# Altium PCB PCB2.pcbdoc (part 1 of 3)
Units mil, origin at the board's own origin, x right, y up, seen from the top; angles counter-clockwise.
Board outline 1771.65 x 2755.61 mil, 4 copper layers (Top Layer, Inner1, Inner2, Bottom Layer), stack 62.447 mil thick; 80 components, 88 nets, 409 pads, 183 vias.
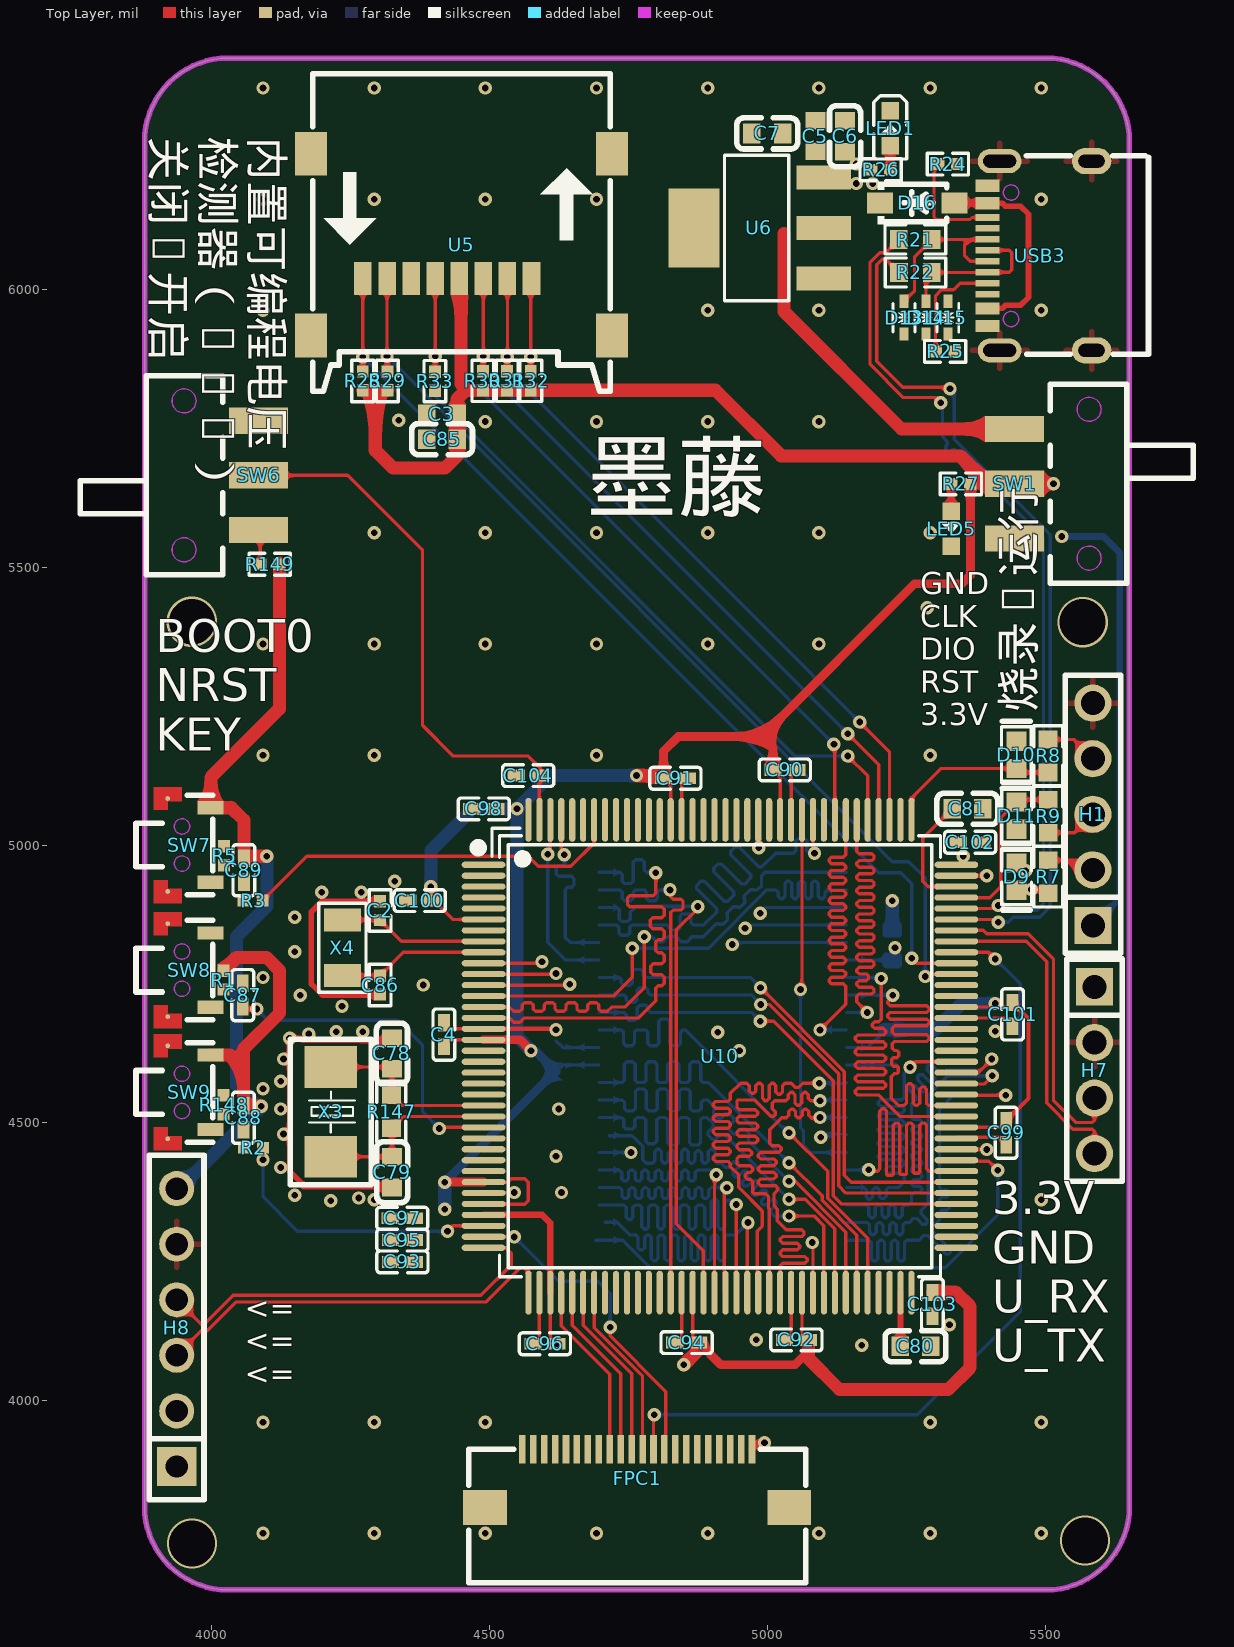
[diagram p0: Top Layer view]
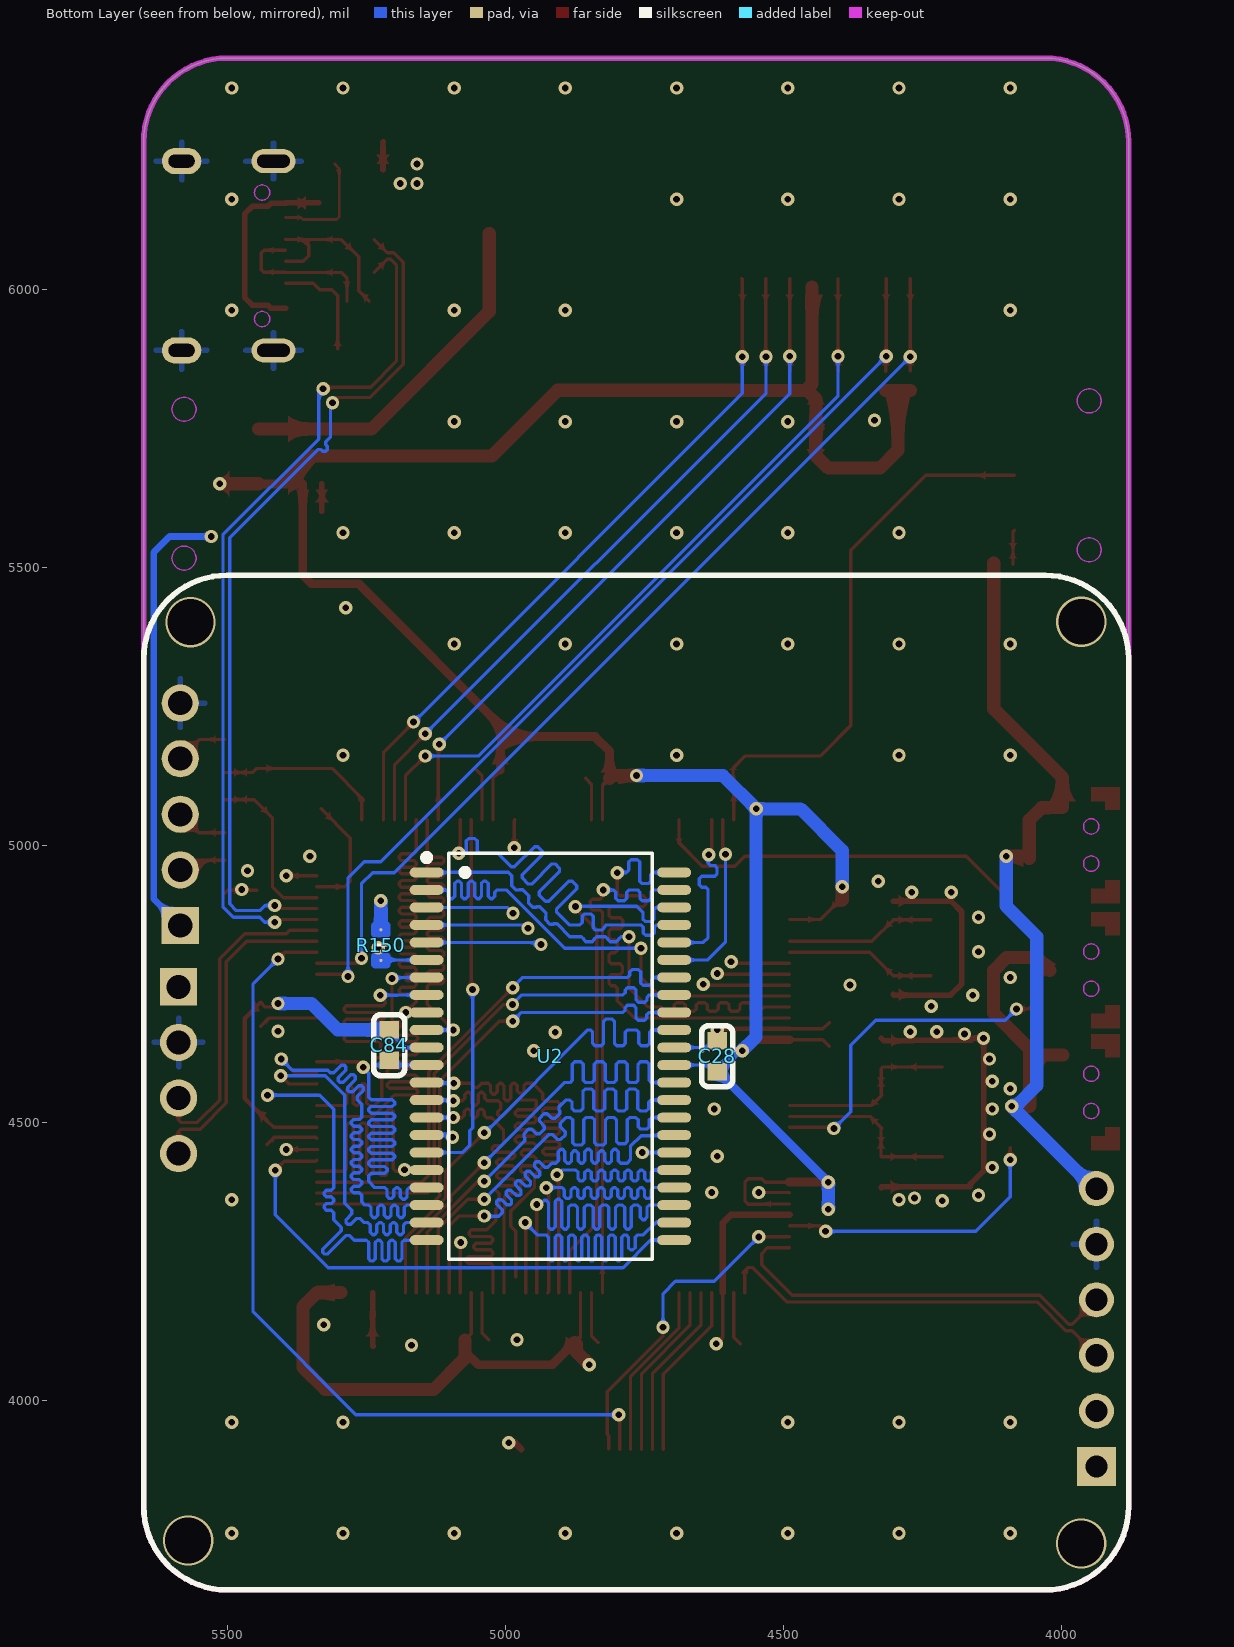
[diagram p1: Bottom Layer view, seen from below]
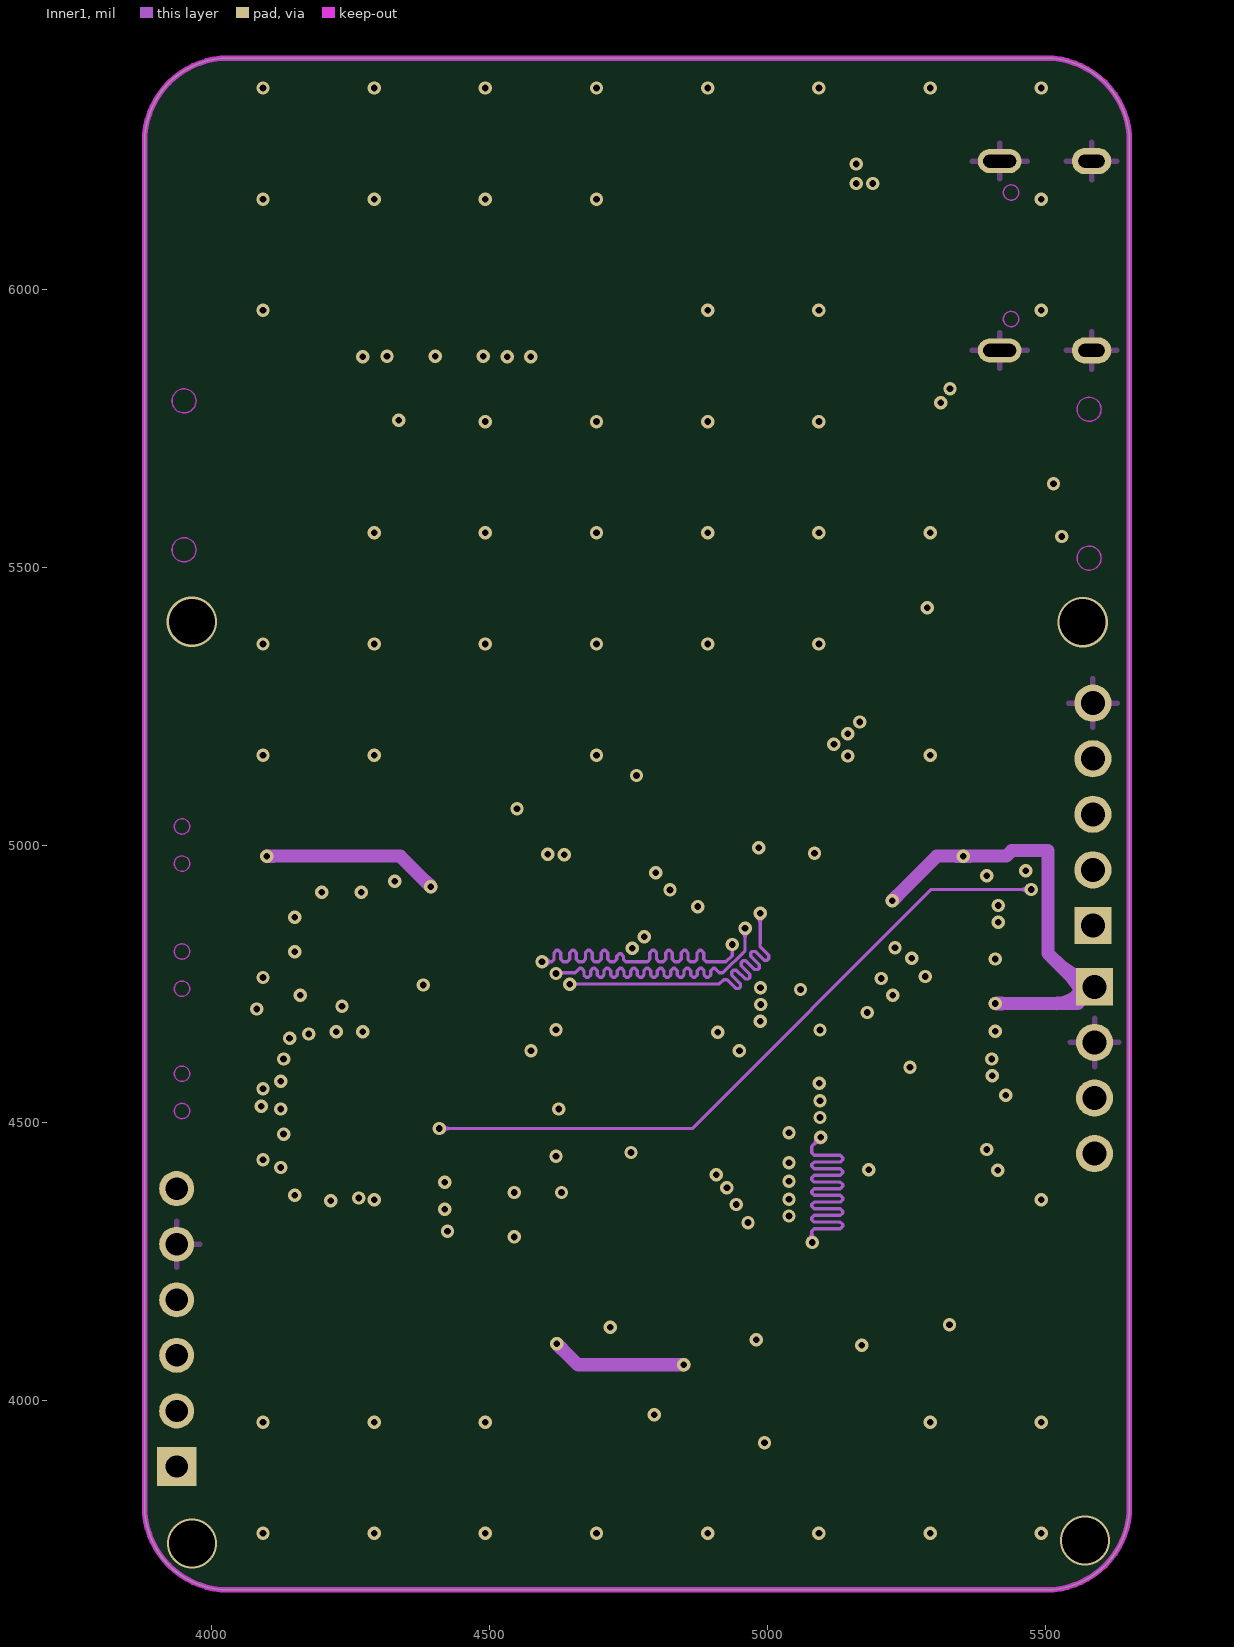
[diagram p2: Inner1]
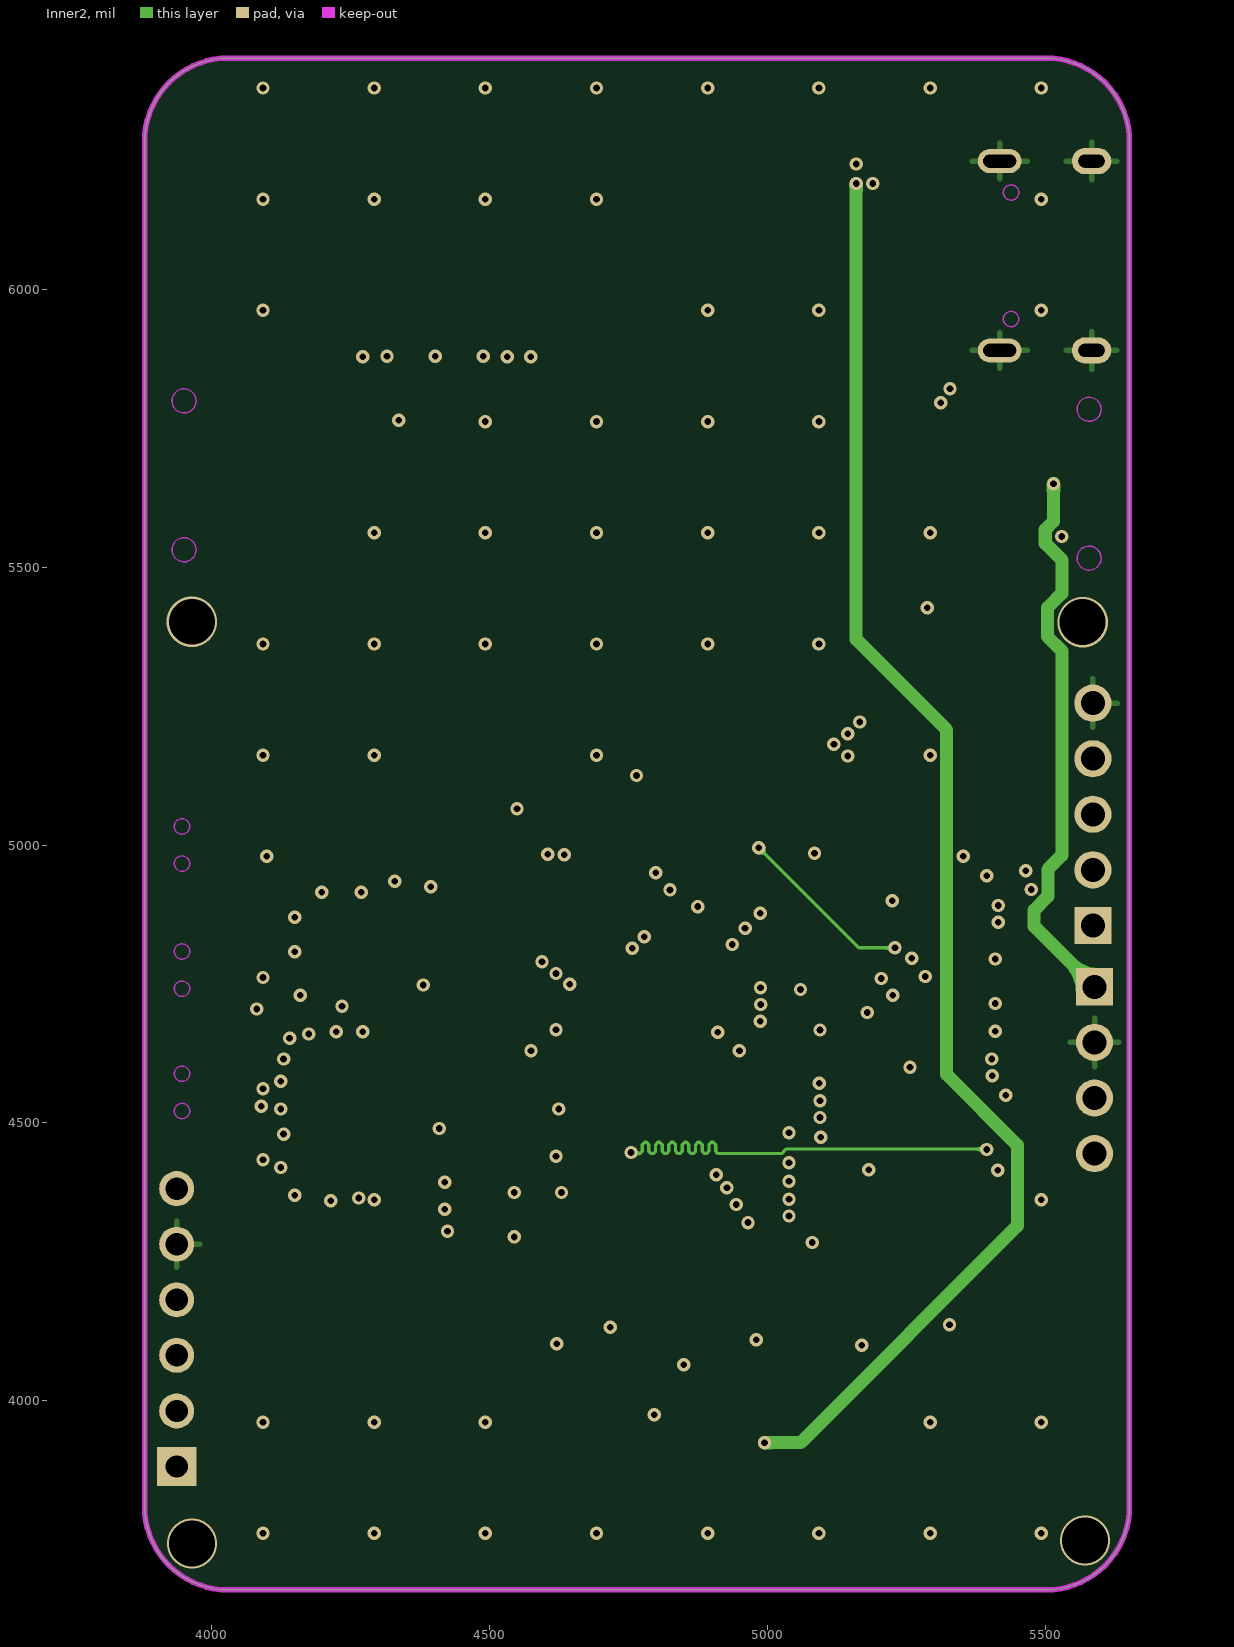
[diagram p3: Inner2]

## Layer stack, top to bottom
Top Layer: signal copper 1.378
Dielectric1: surface 8.283, 7628 RC49% 8.6mil, Dk 0
Inner1: signal copper 0.598
Dielectric2: surface 41.929, 1.1mm H/HOZ Copper, Dk 0
Inner2: signal copper 0.598
Dielectric3: surface 8.283, 7628 RC49% 8.6mil, Dk 0
Bottom Layer: signal copper 1.378

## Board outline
4030,3660 5501.65,3660 ccw(c5501.65,3810) 5651.65,3810 5651.65,6265.61 ccw(c5501.65,6265.61) 5501.65,6415.61 4030,6415.61 ccw(c4030,6265.61) 3880,6265.61 3880,3810 ccw(c4030,3810)

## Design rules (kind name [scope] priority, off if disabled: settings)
BoardOutlineClearance copperThickness1oz [All] p0: genericclearance=10 ignorepadtopadclearanceinfootprint=FALSE except(0: Arc-SplitContinuation Track-SplitContinuation SMDPad-SplitContinuation THPad-SplitContinuation Via-SplitContinuation Fill-SplitContinuation Poly-SplitContinuation Region-SplitContinuation Text-SplitContinuation)
BoardOutlineClearance copperThickness2oz [All] p0: genericclearance=10 ignorepadtopadclearanceinfootprint=FALSE except(0: Arc-SplitContinuation Track-SplitContinuation SMDPad-SplitContinuation THPad-SplitContinuation Via-SplitContinuation Fill-SplitContinuation Poly-SplitContinuation Region-SplitContinuation Text-SplitContinuation)
BoardOutlineClearance Plane_innerPlane [All] p0: genericclearance=10 ignorepadtopadclearanceinfootprint=FALSE except(0: Arc-SplitContinuation Track-SplitContinuation SMDPad-SplitContinuation THPad-SplitContinuation Via-SplitContinuation Fill-SplitContinuation Poly-SplitContinuation Region-SplitContinuation Text-SplitContinuation)
BoardOutlineClearance Copper_copperRegion [All] p0: genericclearance=10 ignorepadtopadclearanceinfootprint=FALSE except(0: Arc-SplitContinuation Track-SplitContinuation SMDPad-SplitContinuation THPad-SplitContinuation Via-SplitContinuation Fill-SplitContinuation Poly-SplitContinuation Region-SplitContinuation Text-SplitContinuation)
BoardOutlineClearance otherClearance [All] p0: genericclearance=10 ignorepadtopadclearanceinfootprint=FALSE except(0: Arc-SplitContinuation Track-SplitContinuation SMDPad-SplitContinuation THPad-SplitContinuation Via-SplitContinuation Fill-SplitContinuation Poly-SplitContinuation Region-SplitContinuation Text-SplitContinuation)
Clearance copperThickness1oz [All] p1: gap=7 ignorepadtopadclearanceinfootprint=FALSE
Clearance copperThickness2oz [All] p1: gap=7 ignorepadtopadclearanceinfootprint=FALSE
Clearance Plane_innerPlane [All] p1: gap=7 ignorepadtopadclearanceinfootprint=FALSE
Clearance Copper_copperRegion [All] p1: gap=7 ignorepadtopadclearanceinfootprint=FALSE
Clearance otherClearance [All] p1: gap=7 ignorepadtopadclearanceinfootprint=FALSE
DiffPairsRouting differentialPair [All] p1: maxuncoupledlength=10 minlimit=6 maxlimit=Infinity mostfreqgap=6 toplayer_minwidth=5 toplayer_prefwidth=10 toplayer_maxwidth=100 bottomlayer_minwidth=5 bottomlayer_prefwidth=10 bottomlayer_maxwidth=100 midlayer1_minwidth=5 midlayer1_prefwidth=10 midlayer1_maxwidth=100 midlayer2_minwidth=5 midlayer2_prefwidth=10 midlayer2_maxwidth=100
PasteMaskExpansion pasteMaskExpansion [All] p1: expansion=0
PlaneConnect innerPlane [All] p1: planeconnectstyle=Relief reliefexpansion=20 reliefentries=4 reliefconductorwidth=10 reliefairgap=10
PolygonConnect copperRegion [All] p1: connectstyle=Relief reliefentries=4 reliefconductorwidth=10 polygonreliefangle="90 Angle" airgapwidth=10
RoutingVias viaSize [All] p1: viastyle="Through Hole" holewidth=12.0078 minholewidth=11.811 maxholewidth=248.0314 width=12.0078 minwidth=11.811 maxwidth=248.0314
SolderMaskExpansion solderMaskExpansion [All] p1: useseparateexpansions=TRUE expansion=2 expansionbottom=2
Width copperThickness1oz [All] p1: maxlimit=100 minlimit=5 preferedwidth=10
Width copperThickness2oz [All] p1: maxlimit=100 minlimit=8 preferedwidth=10

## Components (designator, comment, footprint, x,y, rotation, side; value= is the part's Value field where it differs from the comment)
C2 "" C0402#1 4303.59,4882.12 r270 top
C3 "" C0603 4414.88,5775 r0 top
C4 "" C0402#2 4418.54,4659.04 r270 top
C5 "" C0603 5086.74,6275.27 r270 top
C6 "" C0603 5140,6275 r270 top
C7 "" C0603 5000,6280 r0 top
C28 "" C0603 4620,4620 r90 bottom
C78 "" C0603 4325,4625 r270 top
C79 "" C0603 4325.2,4411.45 r90 top
C80 "" C0603 5266.68,4098.42 r0 top
C81 "" C0603 5360,5065 r0 top
C84 "" C0603 5210,4640 r270 bottom
C85 "" C0603 4415.12,5730 r0 top
C86 "" C0402#1 4303.65,4748.1 r90 top
C87 "" C0402#2 4056.63,4729.95 r270 top
C88 "" C0402#2 4057.66,4509.25 r270 top
C89 "" C0402#2 4058.6,4954.65 r270 top
C90 "" C0402#2 5031.73,5135 r0 top
C91 "" C0402#2 4835,5120 r0 top
C92 "" C0402#2 5052.51,4109.69 r180 top
C93 "" C0402#2 4343.88,4250.12 r180 top
C94 "" C0402#2 4855,4105 r180 top
C95 "" C0402#2 4343.73,4289.34 r180 top
C96 "" C0402#2 4600.16,4102.72 r180 top
C97 "" C0402#2 4343.54,4328.54 r180 top
C98 "" C0402#2 4490,5065 r180 top
C99 "" C0402#2 5429.86,4482.51 r270 top
C100 "" C0402#2 4375,4900 r180 top
C101 "" C0402#2 5441.34,4695.32 r270 top
C102 "" C0402#2 5365,5005 r0 top
C103 "" C0402#2 5297.11,4173.48 r270 top
C104 "" C0402#2 4570,5125 r0 top
D9 "" D0603-BI 5448.5,4943.08 r90 top
D10 "" D0603-BI 5448.3,5162.25 r90 top
D11 "" D0603-BI 5448.63,5052.77 r270 top
D13 "" SOD-523_L1.2-W0.8-LS1.6-BI 5246.2,5948.73 r90 top
D14 "" SOD-523_L1.2-W0.8-LS1.6-BI 5285.77,5948.78 r90 top
D15 "" SOD-523_L1.2-W0.8-LS1.6-BI 5325.02,5948.71 r90 top
D16 "" SOD-123_L2.7-W1.6-LS3.7-RD-1 5270,6155 r0 top
FPC1 "" FPC-SMD_P0.5-22P_FGS-XJ-H2.0 4765.88,3860.62 r180 top
H1 "" HDR-TH_5P-P2.54-V-M 5585.85,5055.26 r90 top
H7 "" HDR-TH_4P-P2.54-V-M 5588.85,4594.91 r270 top
H8 "" HDR-TH_6P-P2.54-V-F 3937.62,4131.93 r90 top
LED1 "" LED0603-RD 5221.17,6288.98 r270 top
LED5 "" LED0603-RD-YELLOW 5331.1,5569.32 r90 top
R1 "" R0402 4021.66,4757.07 r270 top
R2 "" R0402 4075.83,4455.47 r180 top
R3 "" R0402 4075,4900 r180 top
R5 "" R0402 4023.07,4980.87 r90 top
R7 "" R0603#1 5505.62,4943.01 r270 top
R8 "" R0603#1 5505.48,5160.22 r270 top
R9 "" R0603#1 5505.63,5051.96 r90 top
R21 "" R0603#1 5266.49,6089.25 r0 top
R22 "" R0603#1 5266.64,6029.96 r0 top
R24 "" R0402 5325,6225 r0 top
R25 "" R0402 5320.04,5887.86 r0 top
R26 "" R0402 5204.13,6214.77 r180 top
R27 "" R0402 5348.45,5649.57 r0 top
R28 "" R0402 4272.47,5834.86 r270 top
R29 "" R0402 4316.8,5834.81 r270 top
R30 "" R0402 4488.59,5835 r270 top
R31 "" R0402 4532.15,5835.11 r270 top
R32 "" R0402 4574.52,5835.02 r270 top
R33 "" R0402 4402.2,5834.53 r270 top
R147 "" R0603#1 4323.87,4520.27 r90 top
R148 "" R0402 4022.04,4532.96 r90 top
R149 "" R0402 4105,5505 r0 top
R150 "" R0603#2 5225,4820 r270 bottom
SW1 "" SW-SMD_K3-1280S-K1 5445,5650 r0 top
SW6 "" SW-SMD_K3-1280S-K1 4085,5665 r180 top
SW7 "" SW-SMD_2P-TS24CA 3960,5000 r90 top
SW8 "" SW-SMD_2P-TS24CA 3960,4775 r90 top
SW9 "" SW-SMD_2P-TS24CA 3960,4555 r90 top
U2 "" TSOP-44_L18.4-W10.2-P0.80-LS11.8-BL 4920,4620 r270 bottom locked
U5 "" TF-SMD_ZX-TF-281.6J 4450,6080 r0 top
U6 "" SOT-223-3_L6.5-W3.4-P2.30-LS7.0-BR 4985,6110 r0 top
U10 "" LQFP-144_L20.0-W20.0-P0.50-LS22.0-BL 4915,4620 r270 top locked
USB3 "" USB-C-SMD_TYPE-C-6PIN-2MD-073 5490,6060 r90 top
X3 "" OSC-SMD_L5.0-W3.2 4215,4520 r90 top
X4 "" crystal-smd_l3.2-w1.5-1 4235.74,4815.13 r270 top

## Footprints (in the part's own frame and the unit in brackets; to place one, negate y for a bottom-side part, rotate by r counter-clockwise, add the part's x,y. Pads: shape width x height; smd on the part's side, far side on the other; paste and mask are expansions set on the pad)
C0402#1 [mm]
  rect 0.566x0.54 smd: 1(-0.433,0) 2(0.433,0)
  silkscreen extent -0.94,-0.5 0.94,0.5
C0402#2 [mm]
  rect 0.79x0.54 smd: 1(-0.545,0) 2(0.545,0)
  silkscreen extent -1.17,-0.5 1.17,0.5
C0603 [mm]
  rect 0.8x0.9 smd: 1(-0.7,0) 2(0.7,0)
crystal-smd_l3.2-w1.5-1 [mil]
  rect 41.3x66.9 smd: 1(-50.2,0) 2(50.2,0)
  silkscreen extent -80,-43 80,43
D0603-BI [mil]
  rect 34.38x35.72 smd: 1(-24.47,0) 2(24.47,0)
  silkscreen extent -60,-27 60,27
FPC-SMD_P0.5-22P_FGS-XJ-H2.0 [mm]
  rect 0.3x1.3 smd: 1(-5.252,-1.338) 2(-4.752,-1.338) 3(-4.252,-1.338) 4(-3.752,-1.338) 5(-3.252,-1.338) 6(-2.752,-1.338) 7(-2.252,-1.338) 8(-1.752,-1.338) 9(-1.25,-1.339) 10(-0.752,-1.338) 11(-0.252,-1.338) 12(0.248,-1.338) 13(0.748,-1.338) 14(1.248,-1.338) 15(1.748,-1.338) 16(2.248,-1.338) 17(2.748,-1.338) 18(3.248,-1.338) 19(3.748,-1.338) 20(4.25,-1.339) 21(4.748,-1.338) 22(5.248,-1.338)
  rect 2x1.6 smd: 23(6.95,1.339) 24(-6.95,1.339)
  silkscreen extent -7.7,-1.34 7.7,4.76
HDR-TH_4P-P2.54-V-M [mm]
  rect 1.7x1.7 hole 1.1: 1(-3.81,0)
  round 1.7 hole 1.1: 2(-1.27,0) 3(1.27,0) 4(3.81,0)
  silkscreen extent -5.08,-1.27 5.08,1.27
HDR-TH_5P-P2.54-V-M [mm]
  rect 1.7x1.7 hole 1.1: 1(-5.08,0)
  round 1.7 hole 1.1: 2(-2.54,0) 3(0,0) 4(2.54,0) 5(5.08,0)
  silkscreen extent -6.35,-1.27 6.35,1.27
HDR-TH_6P-P2.54-V-F [mm]
  rect 1.8x1.8 hole 1.02: 1(-6.35,0)
  round 1.6 hole 1.02: 2(-3.81,0) 3(-1.27,0) 4(1.27,0) 5(3.81,0) 6(6.35,0)
  silkscreen extent -7.87,-1.25 7.87,1.25
LED0603-RD [mm]
  rect 0.8x0.8 smd: 1(-0.799,0) 2(0.799,0)
  silkscreen extent -1.49,-0.75 1.39,0.76
LED0603-RD-YELLOW [mm]
  rect 0.8x0.8 smd: 1(-0.799,-0.003) 2(0.799,0.003)
  silkscreen extent -0.12,-0.32 0.22,0.36
LQFP-144_L20.0-W20.0-P0.50-LS22.0-BL [mm]
  oval 0.28x2 smd: 1(-8.75,-10.8) 2(-8.25,-10.8) 3(-7.75,-10.8) 4(-7.25,-10.8) 5(-6.75,-10.8) 6(-6.25,-10.8) 7(-5.75,-10.8) 8(-5.25,-10.8) 9(-4.75,-10.8) 10(-4.25,-10.8) 11(-3.75,-10.8) 12(-3.25,-10.8) 13(-2.75,-10.8) 14(-2.25,-10.8) 15(-1.75,-10.8) 16(-1.25,-10.8) 17(-0.75,-10.8) 18(-0.25,-10.8) 19(0.25,-10.8) 20(0.75,-10.8) 21(1.25,-10.8) 22(1.75,-10.8) 23(2.25,-10.8) 24(2.75,-10.8) 25(3.25,-10.8) 26(3.75,-10.8) 27(4.25,-10.8) 28(4.75,-10.8) 29(5.25,-10.8) 30(5.75,-10.8) 31(6.25,-10.8) 32(6.75,-10.8) 33(7.25,-10.8) 34(7.75,-10.8) 35(8.25,-10.8) 36(8.75,-10.8) 73(8.75,10.8) 74(8.25,10.8) 75(7.75,10.8) 76(7.25,10.8) 77(6.75,10.8) 78(6.25,10.8) 79(5.75,10.8) 80(5.25,10.8) 81(4.75,10.8) 82(4.25,10.8) 83(3.75,10.8) 84(3.25,10.8) 85(2.75,10.8) 86(2.25,10.8) 87(1.75,10.8) 88(1.25,10.8) 89(0.75,10.8) 90(0.25,10.8) 91(-0.25,10.8) 92(-0.75,10.8) 93(-1.25,10.8) 94(-1.75,10.8) 95(-2.25,10.8) 96(-2.75,10.8) 97(-3.25,10.8) 98(-3.75,10.8) 99(-4.25,10.8) 100(-4.75,10.8) 101(-5.25,10.8) 102(-5.75,10.8) 103(-6.25,10.8) 104(-6.75,10.8) 105(-7.25,10.8) 106(-7.75,10.8) 107(-8.25,10.8) 108(-8.75,10.8)
  oval 2x0.28 smd: 37(10.8,-8.75) 38(10.8,-8.25) 39(10.8,-7.75) 40(10.8,-7.25) 41(10.8,-6.75) 42(10.8,-6.25) 43(10.8,-5.75) 44(10.8,-5.25) 45(10.8,-4.75) 46(10.8,-4.25) 47(10.8,-3.75) 48(10.8,-3.25) 49(10.8,-2.75) 50(10.8,-2.25) 51(10.8,-1.75) 52(10.8,-1.25) 53(10.8,-0.75) 54(10.8,-0.25) 55(10.8,0.25) 56(10.8,0.75) 57(10.8,1.25) 58(10.8,1.75) 59(10.8,2.25) 60(10.8,2.75) 61(10.8,3.25) 62(10.8,3.75) 63(10.8,4.25) 64(10.8,4.75) 65(10.8,5.25) 66(10.8,5.75) 67(10.8,6.25) 68(10.8,6.75) 69(10.8,7.25) 70(10.8,7.75) 71(10.8,8.25) 72(10.8,8.75) 109(-10.8,8.75) 110(-10.8,8.25) 111(-10.8,7.75) 112(-10.8,7.25) 113(-10.8,6.75) 114(-10.8,6.25) 115(-10.8,5.75) 116(-10.8,5.25) 117(-10.8,4.75) 118(-10.8,4.25) 119(-10.8,3.75) 120(-10.8,3.25) 121(-10.8,2.75) 122(-10.8,2.25) 123(-10.8,1.75) 124(-10.8,1.25) 125(-10.8,0.75) 126(-10.8,0.25) 127(-10.8,-0.25) 128(-10.8,-0.75) 129(-10.8,-1.25) 130(-10.8,-1.75) 131(-10.8,-2.25) 132(-10.8,-2.75) 133(-10.8,-3.25) 134(-10.8,-3.75) 135(-10.8,-4.25) 136(-10.8,-4.75) 137(-10.8,-5.25) 138(-10.8,-5.75) 139(-10.8,-6.25) 140(-10.8,-6.75) 141(-10.8,-7.25) 142(-10.8,-7.75) 143(-10.8,-8.25) 144(-10.8,-8.75)
  silkscreen extent -10.41,-11.25 10.08,10.08
OSC-SMD_L5.0-W3.2 [mm]
  rect 1.9x2.4 smd: 1(-2.05,0) 2(2.05,0)
  silkscreen extent -3.32,-1.85 3.33,1.85
R0402 [mm]
  rect 0.566x0.54 smd: 1(-0.433,0) 2(0.433,0)
R0603#1 [mil]
  rect 31.75x34.02 smd: 1(-29.66,0) 2(29.66,0)
  silkscreen extent -55,-26 55,26
R0603#2 [mil]
  round 5.51 smd: 1(-27.56,0) 2(27.56,0)
  Top Layer region: -35.43,16.93 -19.69,16.93 -18.97,16.89 -18.27,16.75 -17.59,16.54 -16.94,16.25 -16.33,15.88 -15.77,15.44 -15.27,14.94 -14.83,14.38 -14.46,13.77 -14.16,13.12 -13.95,12.44 -13.82,11.73 -13.78,11.02 -13.78,-11.03 -13.82,-11.74 -13.95,-12.44 -14.16,-13.12 -14.46,-13.77 -14.83,-14.38 -15.27,-14.94 -15.77,-15.45 -16.33,-15.88 -16.94,-16.25 -17.59,-16.55 -18.27,-16.76 -18.97,-16.89 -19.69,-16.93 -35.43,-16.93 -36.15,-16.89 -36.85,-16.76 -37.53,-16.55 -38.18,-16.25 -38.79,-15.88 -39.35,-15.45 -39.86,-14.94 -40.29,-14.38 -40.66,-13.77 -40.96,-13.12 -41.17,-12.44 -41.3,-11.74 -41.34,-11.02 -41.34,11.02 -41.3,11.73 -41.17,12.43 -40.96,13.11 -40.66,13.77 -40.29,14.38 -39.86,14.94 -39.35,15.44 -38.79,15.88 -38.18,16.25 -37.53,16.54 -36.85,16.75 -36.15,16.89
  Top Layer region: 19.68,16.93 35.43,16.93 36.14,16.88 36.85,16.75 37.53,16.54 38.18,16.25 38.79,15.88 39.35,15.44 39.85,14.93 40.29,14.37 40.66,13.77 40.95,13.11 41.17,12.43 41.29,11.73 41.34,11.02 41.34,-11.03 41.29,-11.74 41.17,-12.44 40.95,-13.12 40.66,-13.77 40.29,-14.38 39.85,-14.94 39.35,-15.45 38.79,-15.89 38.18,-16.26 37.53,-16.55 36.85,-16.76 36.14,-16.89 35.43,-16.93 19.68,-16.93 18.97,-16.89 18.27,-16.76 17.59,-16.55 16.94,-16.26 16.33,-15.89 15.77,-15.45 15.26,-14.94 14.82,-14.38 14.45,-13.77 14.16,-13.12 13.95,-12.44 13.82,-11.74 13.78,-11.03 13.78,11.02 13.82,11.73 13.95,12.43 14.16,13.11 14.45,13.77 14.82,14.37 15.26,14.93 15.77,15.44 16.33,15.88 16.94,16.25 17.59,16.54 18.27,16.75 18.97,16.88
  silkscreen extent 0,-12 0,12
SOD-123_L2.7-W1.6-LS3.7-RD-1 [mm]
  rect 1.2x0.95 smd: 1(-1.7,0) 2(1.7,0)
  silkscreen extent -1.81,-0.98 1.35,0.98
SOD-523_L1.2-W0.8-LS1.6-BI [mm]
  rect 0.6x0.4 smd: 1(-0.75,0) 2(0.75,0)
  silkscreen extent -0.65,-0.5 0.65,0.5
SOT-223-3_L6.5-W3.4-P2.30-LS7.0-BR [mm]
  rect 2.5x1.1 smd: 1(2.97,-2.3) 2(2.97,0) 3(2.97,2.3)
  rect 2.34x3.6 smd: 4(-2.97,0)
  silkscreen extent -1.57,-3.33 1.37,3.33
SW-SMD_2P-TS24CA [mm]
  rect 0.6x1.2 smd: 1(-1.7,-0.975) 2(1.7,-0.975)
  round 0.21 smd: 3(2.125,0.975) 4(-2.125,0.975)
  Top Layer region: -1.6,0.975 -1.6,1.625 -2.65,1.625 -2.65,0.325 -2,0.325 -2,0.975 -1.6,0.975
  Top Layer region: 2.65,0.325 2.65,1.625 1.6,1.625 1.6,0.975 1.6,0.975 2,0.975 2,0.325
  Board Outline Layer circle w0.003: c0.85,0.325 r0.35
  Board Outline Layer circle w0.003: c-0.85,0.325 r0.35
  Board Outline Layer region: 0.85,-0.025 0.698,0.01 0.576,0.107 0.509,0.247 0.509,0.403 0.576,0.543 0.698,0.64 0.85,0.675 0.85,0.675 1.002,0.64 1.124,0.543 1.191,0.403 1.191,0.247 1.124,0.107 1.002,0.01 0.85,-0.025
  Board Outline Layer region: 0.85,-0.025 0.698,0.01 0.576,0.107 0.509,0.247 0.509,0.403 0.576,0.543 0.698,0.64 0.85,0.675 0.85,0.675 1.002,0.64 1.124,0.543 1.191,0.403 1.191,0.247 1.124,0.107 1.002,0.01 0.85,-0.025
  Board Outline Layer region: -0.85,-0.025 -1.002,0.01 -1.124,0.107 -1.191,0.247 -1.191,0.403 -1.124,0.543 -1.002,0.64 -0.85,0.675 -0.85,0.675 -0.698,0.64 -0.576,0.543 -0.509,0.403 -0.509,0.247 -0.576,0.107 -0.698,0.01 -0.85,-0.025
  Board Outline Layer region: -0.85,-0.025 -1.002,0.01 -1.124,0.107 -1.191,0.247 -1.191,0.403 -1.124,0.543 -1.002,0.64 -0.85,0.675 -0.85,0.675 -0.698,0.64 -0.576,0.543 -0.509,0.403 -0.509,0.247 -0.576,0.107 -0.698,0.01 -0.85,-0.025
  silkscreen extent -2.28,-1.07 2.28,2.43
SW-SMD_K3-1280S-K1 [mm]
  rect 2.7x1.2 smd: 1(0,2.5) 2(0,0) 3(0,-2.5)
  Board Outline Layer circle w0.003: c3.406,3.4 r0.55
  Board Outline Layer circle w0.003: c3.406,-3.4 r0.55
  Board Outline Layer region: 3.956,3.4 3.902,3.161 3.749,2.97 3.529,2.864 3.284,2.864 3.063,2.97 2.911,3.161 2.856,3.4 2.856,3.4 2.911,3.639 3.063,3.83 3.284,3.936 3.529,3.936 3.749,3.83 3.902,3.639 3.956,3.4
  Board Outline Layer region: 3.956,3.4 3.902,3.161 3.749,2.97 3.529,2.864 3.284,2.864 3.063,2.97 2.911,3.161 2.856,3.4 2.856,3.4 2.911,3.639 3.063,3.83 3.284,3.936 3.529,3.936 3.749,3.83 3.902,3.639 3.956,3.4
  Board Outline Layer region: 3.956,-3.4 3.902,-3.639 3.749,-3.83 3.529,-3.936 3.284,-3.936 3.063,-3.83 2.911,-3.639 2.856,-3.4 2.856,-3.4 2.911,-3.161 3.063,-2.97 3.284,-2.864 3.529,-2.864 3.749,-2.97 3.902,-3.161 3.956,-3.4
  Board Outline Layer region: 3.956,-3.4 3.902,-3.639 3.749,-3.83 3.529,-3.936 3.284,-3.936 3.063,-3.83 2.911,-3.639 2.856,-3.4 2.856,-3.4 2.911,-3.161 3.063,-2.97 3.284,-2.864 3.529,-2.864 3.749,-2.97 3.902,-3.161 3.956,-3.4
  silkscreen extent 1.63,-4.55 8.15,4.55
TF-SMD_ZX-TF-281.6J [mm]
  rect 0.8x1.5 smd: 1(3.2,-1.55) 2(2.1,-1.55) 3(1,-1.55) 4(-0.1,-1.55) 5(-1.2,-1.55) 6(-2.3,-1.55) 7(-3.4,-1.55) 8(-4.5,-1.55)
  rect 1.45x2 smd: 9(-6.875,-4.15) 10(6.875,-4.15) 11(6.875,4.15) 12(-6.875,4.15)
  silkscreen extent -6.8,-6.7 6.8,7.8
TSOP-44_L18.4-W10.2-P0.80-LS11.8-BL [mm]
  oval 0.448x1.551 smd: 1(-8.4,-5.656) 2(-7.6,-5.656) 3(-6.8,-5.656) 4(-6,-5.656) 5(-5.2,-5.656) 6(-4.4,-5.656) 7(-3.6,-5.656) 8(-2.8,-5.656) 9(-2,-5.656) 10(-1.2,-5.656) 11(-0.4,-5.656) 12(0.4,-5.656) 13(1.2,-5.656) 14(2,-5.656) 15(2.8,-5.656) 16(3.6,-5.656) 17(4.4,-5.656) 18(5.2,-5.656) 19(6,-5.656) 20(6.8,-5.656) 21(7.6,-5.656) 22(8.4,-5.656) 23(8.4,5.656) 24(7.6,5.656) 25(6.8,5.656) 26(6,5.656) 27(5.2,5.656) 28(4.4,5.656) 29(3.6,5.656) 30(2.8,5.656) 31(2,5.656) 32(1.2,5.656) 33(0.4,5.656) 34(-0.4,5.656) 35(-1.2,5.656) 36(-2,5.656) 37(-2.8,5.656) 38(-3.6,5.656) 39(-4.4,5.656) 40(-5.2,5.656) 41(-6,5.656) 42(-6.8,5.656) 43(-7.6,5.656) 44(-8.4,5.656)
  silkscreen extent -9.28,-5.81 9.28,4.65
USB-C-SMD_TYPE-C-6PIN-2MD-073 [mm]
  rect 0.55x1.1 smd: 1(-3.2,2.375) 2(-2.4,2.375) 11(2.4,2.375) 12(3.2,2.375)
  rect 0.3x1.1 smd: 3(-1.75,2.375) 4(-1.25,2.375) 5(-0.75,2.375) 6(-0.25,2.375) 7(0.25,2.375) 8(0.75,2.375) 9(1.25,2.375) 10(1.75,2.375)
  oval 1.2x1.8 hole 0.6 slot 1.2 at 90 deg: 13(-4.325,-2.375) 14(4.325,-2.375)
  oval 1.1x2 hole 0.6 slot 1.5 at 90 deg: 13(-4.325,1.825) 14(4.325,1.825)
  Board Outline Layer circle w0.003: c-2.89,1.305 r0.35
  Board Outline Layer circle w0.003: c2.89,1.305 r0.35
  Board Outline Layer region: -2.89,0.955 -3.042,0.99 -3.164,1.087 -3.231,1.227 -3.231,1.383 -3.164,1.523 -3.042,1.62 -2.89,1.655 -2.89,1.655 -2.738,1.62 -2.616,1.523 -2.549,1.383 -2.549,1.227 -2.616,1.087 -2.738,0.99 -2.89,0.955
  Board Outline Layer region: -2.89,0.955 -3.042,0.99 -3.164,1.087 -3.231,1.227 -3.231,1.383 -3.164,1.523 -3.042,1.62 -2.89,1.655 -2.89,1.655 -2.738,1.62 -2.616,1.523 -2.549,1.383 -2.549,1.227 -2.616,1.087 -2.738,0.99 -2.89,0.955
  Board Outline Layer region: 2.89,0.955 2.738,0.99 2.616,1.087 2.549,1.227 2.549,1.383 2.616,1.523 2.738,1.62 2.89,1.655 2.89,1.655 3.042,1.62 3.164,1.523 3.231,1.383 3.231,1.227 3.164,1.087 3.042,0.99 2.89,0.955
  Board Outline Layer region: 2.89,0.955 2.738,0.99 2.616,1.087 2.549,1.227 2.549,1.383 2.616,1.523 2.738,1.62 2.89,1.655 2.89,1.655 3.042,1.62 3.164,1.523 3.231,1.383 3.231,1.227 3.164,1.087 3.042,0.99 2.89,0.955
  silkscreen extent -4.5,-4.97 4.57,0.6

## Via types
v1: diameter 24.02, hole 12.01, Top Layer to Bottom Layer, 179 vias
v2: diameter 90.55, hole 82.68, Top Layer to Bottom Layer, 4 vias

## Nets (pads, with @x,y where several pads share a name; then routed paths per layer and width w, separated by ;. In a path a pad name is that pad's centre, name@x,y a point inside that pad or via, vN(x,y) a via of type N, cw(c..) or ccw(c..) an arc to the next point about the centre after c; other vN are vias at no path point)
3.3V: C3.2 C4.2 C28.1 C84.1 C85.2 C88.1 C89.1 C90.1 C91.1 C92.1 C93.1 C94.1 C95.1 C96.1 C97.1 C98.1 C99.1 C100.1 C101.1 C102.1 C103.1 H7.1 H8.6 R1.1 R27.2 R28.2 R29.2 R30.2 R31.2 R32.2 R149.2 R150.1 SW1.2 SW7.2 SW9.2 U2.11 U2.33 U5.4 U10.6 U10.17 U10.30 U10.32 U10.33 U10.39 U10.52 U10.62 U10.72 U10.84 U10.95 U10.108 U10.121 U10.131 U10.144 | length 11374.2
  Top Layer w6: C100.1@4400,4900 4433.94,4866.06 U10.6@4489.8,4866.06 ; C4.2@4418.54,4637.58 4430.49,4649.53 U10.17@4489.8,4649.53 ; U10.32@4489.8,4354.25 4536.06,4354.25 4536.3,4354.01 4564.01,4354.01 4570,4360 4570,4393.62 4564,4399.62 4539.62,4399.62 4533.62,4393.62 U10.30@4489.8,4393.62 ; U10.39@4609.88,4194.8 4609.88,4114.45 v1(4621.62,4102.72) ; C91.1@4813.54,5120 4826.42,5107.12 U10.131@4826.42,5045.2 ; U10.52@4865.79,4194.8 4865.79,4115.67 C94.1@4876.46,4105 ; C90.1@5010.27,5135 5023.27,5122 U10.121@5023.27,5045.2 ; U10.62@5062.64,4194.8 5062.64,4121.01 C92.1@5073.97,4109.69 ; U10.84@5340.2,4492.05 5417.94,4492.05 C99.1@5429.86,4503.97 ; U10.95@5340.2,4708.58 5433.14,4708.58 C101.1@5441.34,4716.78
  Top Layer w7.87: C99.1@5429.86,4503.97 5470,4544.11 5470,4688.12 C101.1@5441.34,4716.78
  Top Layer w11.81: U10.33@4489.8,4334.57 4595.43,4334.57 4609.88,4320.12 U10.39@4609.88,4194.8
  Top Layer w15.75: v1(4420,4393.62) U10.30@4489.8,4393.62 ; U10.17@4489.8,4649.53 4555.47,4649.53 v1(4575,4630) ; C91.1@4813.54,5120 4813.54,5168.54 4840,5195 4990,5195 ; C94.1@4876.46,4105 4916.46,4065 5050,4065 5073.97,4088.97 ; C90.1@5010.27,5135 5010.27,5174.73 4990,5195 ; SW1.2@5445,5650 5444.57,5649.57 R27.2@5365.49,5649.57 5365.49,5485.75 5349.74,5470 5265,5470 4990,5195
  Top Layer w23.62: SW9.2@3998.39,4621.93 4033.07,4621.93 4057.66,4597.34 ; R1.1@4021.66,4774.11 4045.28,4797.73 4099.21,4797.73 4122.83,4774.11 4122.83,4697.83 4057.66,4632.66 4057.66,4597.34 ; v1(4090,4530) 4058.37,4530 C88.1@4057.66,4530.71 4057.66,4597.34 ; v1(4100,4980) 4062.49,4980 C89.1@4058.6,4976.11 4058.6,5045.02 4036.22,5067.39 3999.22,5067.39 3999.22,5121.66 4122.39,5244.84 4122.39,5348.95 4122.83,5349.38 4122.83,5374.07 4122.39,5374.51 R149.2@4122.39,5506.8 ; R28.2@4272.47,5817.82 R29.2@4316.8,5817.77 ; R29.2@4316.8,5817.77 4295,5817.77 4295,5710 4327.04,5677.96 4420,5677.96 4442.68,5700.64 C85.2@4442.68,5730 4442.44,5730.24 C3.2@4442.44,5775 4442.44,5802.44 4457.96,5817.96 R30.2@4488.59,5817.96 R32.2@4574.52,5817.98 ; v1(4395,4925) 4395,4901.46 C100.1@4396.46,4900 ; U5.4@4449.17,6003.57 4449.17,5829.6 4459.45,5819.32 ; R32.2@4574.52,5817.98 4907.02,5817.98 5025,5700 5347.7,5700 5391.81,5655.88 ; v1(4765,5125) 4808.54,5125 C91.1@4813.54,5120 ; v1(4850,4065) 4873.62,4088.62 4873.62,4102.16 C94.1@4876.46,4105 ; C92.1@5073.97,4109.69 5073.97,4088.97 5073.97,4076.58 5130,4020.54 5325.54,4020.54 5365,4060 5365,4170 5340.06,4194.94 C103.1@5297.11,4194.94 ; SW1.2@5445,5650 v1(5515,5650)
  Inner1 w23.62: v1(4100,4980) 4340,4980 v1(4395,4925) ; v1(4621.62,4102.72) 4659.33,4065 v1(4850,4065) ; v1(5225,4900) 5305,4980 v1(5352.63,4980) 5430,4980 5440,4990 5505,4990 5505,4805 5565.09,4744.91 H7.1@5588.85,4744.91 5558.94,4715 v1(5410,4715)
  Inner2 w23.62: v1(5515,5650) 5515,5582.15 5500.2,5567.34 5500.2,5542.66 5530,5512.85 5530,5452.88 5504.28,5427.16 5504.28,5374.91 5530,5349.19 5530,4981.33 5504.8,4956.13 5504.8,4907.66 5480,4882.85 5480,4853.76 H7.1@5588.85,4744.91
  Bottom Layer w6: C28.1@4620,4592.44 4631.81,4604.25 U2.33@4697.34,4604.25 ; U2.11@5142.66,4635.75 5180.75,4635.75 C84.1@5207.56,4662.56
  Bottom Layer w15.75: v1(4420,4393.62) 4618.82,4592.44 C28.1@4620,4592.44 4582.44,4630 v1(4575,4630)
  Bottom Layer w23.62: H8.6@3937.62,4381.93 3941.93,4381.93 v1(4090,4530) 4088.07,4531.93 4080.68,4531.93 4045,4567.61 4045,4835 4100,4890 v1(4100,4980) ; v1(4395,4925) 4395,4990 4470,5065 v1(4550,5065) ; v1(4420,4345) v1(4420,4393.62) ; v1(4575,4630) 4550,4655 v1(4550,5065) ; v1(4765,5125) 4610,5125 v1(4550,5065) ; C84.1@5210,4667.56 5302.56,4667.56 5350,4715 v1(5410,4715) ; R150.1@5225,4847.56 v1(5225,4900)
5V_USB: C5.2 C6.2 D16.1 FPC1.1 FPC1.2 FPC1.3 FPC1.4 FPC1.5 FPC1.6 FPC1.7 FPC1.8 R26.2 U6.3 | length 2638.9
  Top Layer w11.81: FPC1.1@4972.65,3913.29 4984.36,3925 v1(4995,3925)
  Inner2 w23.62: v1(4995,3925) 5060,3925 5450,4315 5450,4460 5322.83,4587.17 5322.83,5207.17 5160,5370 v1(5160,6190)
  other v1: 5190,6190 5160,6225
$1N4201: D15.2 D16.2 USB3.2 USB3.11 | length 372.9
  Top Layer w10: D16.2@5336.93,6155 5395.99,6155 USB3.11@5396.49,6154.49 5422.89,6154.49 5428.37,6149.02 5455.98,6149.02 5470,6135 5470,5985 5455.99,5970.99 5428.37,5970.99 5422.89,5965.52 USB3.2@5396.49,5965.52
$1N4322: R25.1 USB3.4 | length 199
  Top Layer w6: R25.1@5302.85,5892.37 5302.85,5988.46 5313.42,5999.03 5335.16,5999.03 5346.92,6010.8 USB3.4@5396.49,6010.8
$1N4327: D13.2 R21.2 USB3.6 USB3.8 | length 311.1
  Top Layer w5.98: D13.2@5246.2,5978.25 5265,5997.05 5265,6058.1 R21.2@5296.15,6089.25 5365.19,6089.25 ; USB3.6@5396.49,6050.15 5365,6050.15 5355,6060.15 5355,6079.06 5365.19,6089.25 ; USB3.8@5396.49,6089.52 5396.22,6089.25 5365.19,6089.25
$1N4333: D14.2 R22.2 USB3.5 USB3.7 | length 277.4
  Top Layer w5.98: D14.2@5285.77,5978.3 5285.77,6019.43 R22.2@5296.3,6029.96 5395.98,6029.96 USB3.5@5396.49,6030.48 5435.48,6030.48 5440,6035 5440,6065 5435,6070 5396.65,6070 USB3.7@5396.49,6069.85
$1N4479: R24.1 USB3.10 | length 198.5
  Top Layer w5: R24.1@5307.96,6225 5300,6217.04 5300,6130 5305,6125 5365,6125 5368.9,6128.9 USB3.10@5396.49,6128.9
$1N4593: C7.1 SW1.1 U6.2 U6.4 | length 642.6
  Top Layer w23.62: 5030,6100 5030,5960 5241.58,5748.42 SW1.1@5445,5748.42
$1N4774: H1.1 SW1.3 | length 806.6
  Bottom Layer w11.81: v1(5530,5555) 5605,5555 5633.94,5526.06 5633.94,4903.34 H1.1@5585.85,4855.26
$1N5998: LED1.2 R26.1 | length 43.2
  Top Layer w10: LED1.2@5220.83,6264.77 LED1.2@5221.17,6264.43 ; R26.1@5221.17,6214.77 LED1.2@5221.18,6257.51
$1N6126: LED5.2 R27.1 | length 49
  Top Layer w10: LED5.2@5330.97,5600.79 5330.97,5649.13 R27.1@5331.41,5649.57
$1N20074: C86.2 U10.9 X4.2 | length 271.5
  Top Layer w5.98: X4.2@4235.74,4764.93 4303.43,4764.93 C86.2@4303.65,4765.14 4345.51,4807.01 U10.9@4489.8,4807.01
$1N20111: C2.2 U10.8 X4.1 | length 270.1
  Top Layer w5.98: X4.1@4235.74,4865.33 4303.35,4865.33 C2.2@4303.59,4865.08 4341.98,4826.69 U10.8@4489.8,4826.69
$1N25234: C88.2 R2.2 R148.1 SW9.1
$1N25235: C89.2 R3.2 R5.1 SW7.1
$1N46396: C80.1 U10.71 | length 96.7
  Top Layer w10: C80.1@5239.12,4098.42 5239.8,4099.1 U10.71@5239.8,4194.8
$1N46400: C81.1 U10.106 | length 216.3
  Top Layer w6: C81.1@5332.44,5065 5280,5012.56 5280,4934.69 5289.69,4925 5340.08,4925 U10.106@5340.2,4925.12
$1N46552: C104.2 SW6.2 U10.143 | length 1002.9
  Top Layer w5.98: U10.143@4590.2,5045.2 4590.2,5123.74 C104.2@4591.46,5125
  Top Layer w6: SW6.2@4085,5665 4245,5665 4380,5530 4380,5215 4435,5160 4570,5160 4591.46,5138.54 C104.2@4591.46,5125
$1N46566: R149.1 SW6.1 | length 62.8
  Top Layer w5.98: SW6.1@4085,5566.58 4087.96,5563.62 R149.1@4087.96,5505
A0: U2.5 U10.10 | length 946.2
  Top Layer w6: U10.10@4489.8,4787.32 4592.32,4787.32 v1(4595,4790)
  Inner1 w6: v1(4595,4790) 4612.26,4790 4616.5,4794.24 4616.5,4806.16 4620.75,4810.41 4624.26,4810.41 4628.5,4806.16 4628.5,4794.24 4632.75,4790 4640.5,4790 4644.75,4794.24 4644.75,4806.16 4648.99,4810.41 4652.5,4810.41 4656.75,4806.16 4656.75,4794.24 4660.99,4790 4668.75,4790 4672.99,4794.24 4672.99,4806.16 4677.23,4810.41 4680.75,4810.41 4684.99,4806.16 4684.99,4794.24 4689.23,4790 4696.99,4790 4701.23,4794.24 4701.23,4806.16 4705.47,4810.41 4708.99,4810.41 4713.23,4806.16 4713.23,4794.24 4717.47,4790 4725.23,4790 4729.47,4794.24 4729.47,4800.29 4733.72,4804.53 4737.23,4804.53 4741.47,4800.29 4741.47,4794.24 4745.72,4790 4784.74,4790 4788.98,4794.24 4788.98,4806.16 4793.22,4810.41 4796.74,4810.41 4800.98,4806.16 4800.98,4794.24 4805.22,4790 4812.98,4790 4817.22,4794.24 4817.22,4806.16 4821.47,4810.41 4824.98,4810.41 4829.22,4806.16 4829.22,4794.24 4833.47,4790 4841.22,4790 4845.47,4794.24 4845.47,4806.16 4849.71,4810.41 4853.22,4810.41 4857.47,4806.16 4857.47,4794.24 4861.71,4790 4869.47,4790 4873.71,4794.24 4873.71,4806.16 4877.95,4810.41 4881.47,4810.41 4885.71,4806.16 4885.71,4794.24 4889.95,4790 4925.84,4790 4936.86,4801.03 v1(4936.86,4821.12)
  Bottom Layer w6: v1(4936.86,4821.12) 4940.47,4824.72 U2.5@5142.66,4824.72
A1: U2.4 U10.11 | length 947.5
  Top Layer w6: U10.11@4489.8,4767.64 4618.7,4767.64 v1(4620,4768.94)
  Inner1 w6: v1(4620,4768.94) 4621.31,4770.25 4654.57,4770.25 4662.54,4778.23 4666.06,4778.23 4670.3,4773.98 4670.3,4766.11 4674.54,4761.87 4678.06,4761.87 4682.3,4766.11 4682.3,4773.98 4686.54,4778.23 4690.06,4778.23 4694.3,4773.98 4694.3,4766.11 4698.54,4761.87 4702.06,4761.87 4706.3,4766.11 4706.3,4773.98 4710.54,4778.23 4714.06,4778.23 4718.3,4773.98 4718.3,4766.11 4722.54,4761.87 4726.06,4761.87 4730.3,4766.11 4730.3,4773.98 4734.54,4778.23 4738.06,4778.23 4742.3,4773.98 4742.3,4766.11 4746.54,4761.87 4750.06,4761.87 4754.3,4766.11 4754.3,4773.98 4758.54,4778.23 4762.06,4778.23 4766.3,4773.98 4766.3,4766.11 4770.54,4761.87 4774.06,4761.87 4778.3,4766.11 4778.3,4773.98 4782.54,4778.23 4786.06,4778.23 4790.3,4773.98 4790.3,4766.11 4794.54,4761.87 4798.06,4761.87 4802.3,4766.11 4802.3,4773.98 4806.54,4778.23 4810.06,4778.23 4814.3,4773.98 4814.3,4766.11 4818.54,4761.87 4822.06,4761.87 4826.3,4766.11 4826.3,4773.98 4830.54,4778.23 4834.06,4778.23 4838.3,4773.98 4838.3,4766.11 4842.54,4761.87 4846.06,4761.87 4850.3,4766.11 4850.3,4773.98 4854.54,4778.23 4858.06,4778.23 4862.3,4773.98 4862.3,4766.11 4866.54,4761.87 4870.06,4761.87 4874.3,4766.11 4874.3,4773.98 4878.54,4778.23 4882.06,4778.23 4886.3,4773.98 4886.3,4766.11 4890.54,4761.87 4894.06,4761.87 4898.3,4766.11 4898.3,4773.98 4902.54,4778.23 4906.06,4778.23 4914.03,4770.25 4920.25,4770.25 4960.19,4810.19 v1(4960.19,4850.5)
  Bottom Layer w6: v1(4960.19,4850.5) 4965.91,4856.22 U2.4@5142.66,4856.22
A2: U2.3 U10.12 | length 946.9
  Top Layer w6: U10.12@4489.8,4747.95 4643.72,4747.95 v1(4645.03,4749.26)
  Inner1 w6: v1(4645.03,4749.26) 4645.77,4750 4914.16,4750 4921.76,4757.6 4927.76,4757.6 4943.35,4742.01 4949.35,4742.01 4951.84,4744.5 4951.84,4750.5 4936.25,4766.08 4936.25,4772.08 4938.73,4774.57 4944.73,4774.57 4960.32,4758.98 4966.32,4758.98 4968.81,4761.47 4968.81,4767.47 4953.22,4783.06 4953.22,4789.06 4955.71,4791.54 4961.71,4791.54 4977.29,4775.95 4983.29,4775.95 4985.78,4778.44 4985.78,4784.44 4970.19,4800.03 4970.19,4806.03 4972.68,4808.51 4978.68,4808.51 4994.26,4792.92 5000.26,4792.92 5002.75,4795.41 5002.75,4801.41 4987.16,4817 4987.16,4823 4987.3,4823.13 v1(4987.3,4877.21)
  Bottom Layer w6: v1(4987.3,4877.21) 4997.81,4887.72 U2.3@5142.66,4887.72
A3: U2.2 U10.13 | length 946.4
  Top Layer w6: U10.13@4489.8,4728.27 4723.27,4728.27 4757.06,4762.06 v1(4757.06,4814.4)
  Bottom Layer w6: v1(4757.06,4814.4) 4769.8,4814.4 4769.96,4814.24 4787.35,4814.24 4787.51,4814.4 4894.4,4814.4 4999.21,4919.21 5015.77,4919.21 5020.01,4914.97 5020.01,4907.49 5024.25,4903.25 5027.77,4903.25 5032.01,4907.49 5032.01,4930.93 5036.25,4935.17 5039.77,4935.17 5044.01,4930.93 5044.01,4907.49 5048.25,4903.25 5051.77,4903.25 5056.01,4907.49 5056.01,4930.93 5060.25,4935.17 5063.77,4935.17 5068.01,4930.93 5068.01,4907.49 5072.25,4903.25 5075.77,4903.25 5080.01,4907.49 5080.01,4930.93 5084.25,4935.17 5087.77,4935.17 5092.01,4930.93 5092.01,4907.49 5096.25,4903.25 5099.77,4903.25 5104.01,4907.49 5104.01,4914.97 5108.25,4919.21 U2.2@5142.66,4919.21
A4: U2.1 U10.14 | length 945
  Top Layer w6: U10.14@4489.8,4708.58 4535.99,4708.58 4543.86,4700.71 4555.06,4700.71 4559.31,4704.95 4559.31,4712.21 4563.55,4716.45 4574.75,4716.45 4578.99,4712.21 4578.99,4704.95 4583.23,4700.71 4594.43,4700.71 4598.68,4704.95 4598.68,4712.21 4602.92,4716.45 4614.12,4716.45 4618.36,4712.21 4618.36,4704.95 4622.6,4700.71 4633.8,4700.71 4638.05,4704.95 4638.05,4712.21 4642.29,4716.45 4653.49,4716.45 4657.73,4712.21 4657.73,4704.95 4661.97,4700.71 4673.17,4700.71 4677.42,4704.95 4677.42,4712.21 4681.66,4716.45 4692.86,4716.45 4697.1,4712.21 4697.1,4704.95 4701.34,4700.71 4712.54,4700.71 4720.42,4708.58 4743.58,4708.58 4778.65,4743.65 v1(4778.65,4835.23)
  Bottom Layer w6: v1(4778.65,4835.23) 4792.86,4835.23 4797.1,4830.99 4797.1,4830.41 4801.35,4826.17 4812.55,4826.17 4816.79,4830.41 4816.79,4830.99 4821.03,4835.23 4836.48,4835.23 4840.72,4830.99 4840.72,4830.41 4844.96,4826.17 4856.16,4826.17 4860.4,4830.41 4860.4,4830.99 4864.65,4835.23 4885.23,4835.23 4908.08,4858.08 4914.08,4858.08 4914.75,4857.4 4920.75,4857.4 4928.67,4865.32 4928.67,4871.32 4928,4872 4928,4878 4938.92,4888.92 4944.92,4888.92 4945.59,4888.24 4951.59,4888.24 4959.51,4896.16 4959.51,4902.16 4958.84,4902.84 4958.84,4908.84 4969.76,4919.76 4975.76,4919.76 4976.43,4919.08 4982.43,4919.08 4989.74,4926.39 4989.74,4944.65 4995.79,4950.71 U2.1@5142.66,4950.71
A5: U2.44 U10.15 | length 949.2
  Top Layer w6: U10.15@4489.8,4688.9 4536.22,4688.9 4544.09,4681.03 4555.29,4681.03 4563.17,4688.9 4768.9,4688.9 4799.65,4719.65 4799.65,4742.63 4803.89,4746.87 4810.4,4746.87 4814.65,4751.12 4814.65,4762.32 4810.4,4766.56 4794.67,4766.56 4790.43,4770.8 4790.43,4782 4794.67,4786.24 4810.4,4786.24 4814.65,4790.49 4814.65,4801.69 4810.4,4805.93 4803.89,4805.93 4799.65,4810.17 4799.65,4825.61 4803.89,4829.86 4810.4,4829.86 4814.65,4834.1 4814.65,4845.3 4810.4,4849.54 4794.03,4849.54 4789.78,4853.78 4789.78,4864.98 4794.03,4869.23 4810.4,4869.23 4814.65,4873.47 4814.65,4884.67 4810.4,4888.91 4752.82,4888.91 4748.58,4893.16 4748.58,4904.35 4752.82,4908.6 4795.4,4908.6 4799.65,4912.84 v1(4799.65,4950.35)
  Bottom Layer w6: U2.44@4697.34,4950.71 4735.22,4950.71 4739.47,4946.47 4739.47,4934.87 4743.71,4930.63 4754.91,4930.63 4759.15,4934.87 4759.15,4969.55 4763.4,4973.79 4774.59,4973.79 4778.84,4969.55 4778.84,4954.95 4783.08,4950.71 4799.29,4950.71 v1(4799.65,4950.35)
A6: U2.43 U10.50 | length 944.6
  Top Layer w6: v1(4825,4919.21) 4826.42,4917.79 4826.42,4906.95 4830.66,4902.71 4844.28,4902.71 4848.52,4898.47 4848.52,4887.27 4844.28,4883.03 4830.66,4883.03 4826.42,4878.78 U10.50@4826.42,4194.8
  Bottom Layer w6: U2.43@4697.34,4919.21 4734.94,4919.21 4739.18,4914.97 4739.18,4904.06 4743.42,4899.82 4754.62,4899.82 4758.86,4904.06 4758.86,4914.97 4763.11,4919.21 4778.55,4919.21 4782.79,4914.97 4782.79,4904.06 4787.03,4899.82 4798.23,4899.82 4802.48,4904.06 4802.48,4914.97 4806.72,4919.21 v1(4825,4919.21)
A7: U2.42 U10.53 | length 946.3
  Top Layer w6: v1@4876.48,4887.48 4836.44,4847.43 4836.44,4318.56 4885,4270 4885,4195.27 U10.53@4885.47,4194.8
  Bottom Layer w6: U2.42@4697.34,4887.72 4729.52,4887.72 4733.77,4883.48 4733.77,4866.68 4738.01,4862.44 4749.21,4862.44 4753.45,4866.68 4753.45,4878.87 4764.39,4889.81 4874.47,4889.81 v1(4875.02,4889.26)
A8: U2.27 U10.54 | length 604.4
  Top Layer w6: U10.54@4905.16,4194.8 4905.16,4403.7 v1(4908.07,4406.61)
  Bottom Layer w6: U2.27@4697.34,4415.28 4734.11,4415.28 4738.35,4411.04 4738.35,4399.8 4742.6,4395.55 4746.11,4395.55 4750.35,4399.8 4750.35,4411.04 4754.6,4415.28 4758.11,4415.28 4762.35,4411.04 4762.35,4399.8 4766.6,4395.55 4770.11,4395.55 4774.35,4399.8 4774.35,4411.04 4778.6,4415.28 4782.11,4415.28 4786.35,4411.04 4786.35,4399.8 4790.6,4395.55 4794.11,4395.55 4798.35,4399.8 4798.35,4411.04 4802.6,4415.28 4806.11,4415.28 4810.35,4411.04 4810.35,4399.8 4814.6,4395.55 4818.11,4395.55 4822.35,4399.8 4822.35,4411.04 4826.6,4415.28 4830.11,4415.28 4834.35,4411.04 4834.35,4399.8 4838.6,4395.55 4842.11,4395.55 4846.35,4399.8 4846.35,4411.04 4850.6,4415.28 4854.11,4415.28 4858.35,4411.04 4858.35,4399.8 4862.6,4395.55 4866.11,4395.55 4870.35,4399.8 4870.35,4411.04 4874.6,4415.28 4899.41,4415.28 v1(4908.07,4406.61)
A9: U2.26 U10.55 | length 628.4
  Top Layer w6: U10.55@4924.84,4194.8 4922.86,4196.78 4922.86,4378.97 v1(4927.52,4383.63)
  Bottom Layer w6: U2.26@4697.34,4383.78 4734.6,4383.78 4738.84,4379.54 4738.84,4368.3 4743.09,4364.05 4746.6,4364.05 4750.84,4368.3 4750.84,4379.54 4755.09,4383.78 4758.6,4383.78 4762.84,4379.54 4762.84,4368.3 4767.09,4364.05 4770.6,4364.05 4774.84,4368.3 4774.84,4379.54 4779.09,4383.78 4782.6,4383.78 4786.84,4379.54 4786.84,4368.3 4791.09,4364.05 4794.6,4364.05 4798.84,4368.3 4798.84,4379.54 4803.09,4383.78 4806.6,4383.78 4810.84,4379.54 4810.84,4368.3 4815.09,4364.05 4818.6,4364.05 4822.84,4368.3 4822.84,4379.54 4827.09,4383.78 4830.6,4383.78 4834.84,4379.54 4834.84,4368.3 4839.09,4364.05 4842.6,4364.05 4846.84,4368.3 4846.84,4379.54 4851.09,4383.78 4854.6,4383.78 4858.84,4379.54 4858.84,4368.3 4863.09,4364.05 4866.6,4364.05 4870.84,4368.3 4870.84,4379.54 4875.09,4383.78 4878.6,4383.78 4882.84,4379.54 4882.84,4368.3 4887.09,4364.05 4890.6,4364.05 4894.84,4368.3 4894.84,4379.54 4899.09,4383.78 4917.21,4383.78 4917.36,4383.63 v1(4927.52,4383.63)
